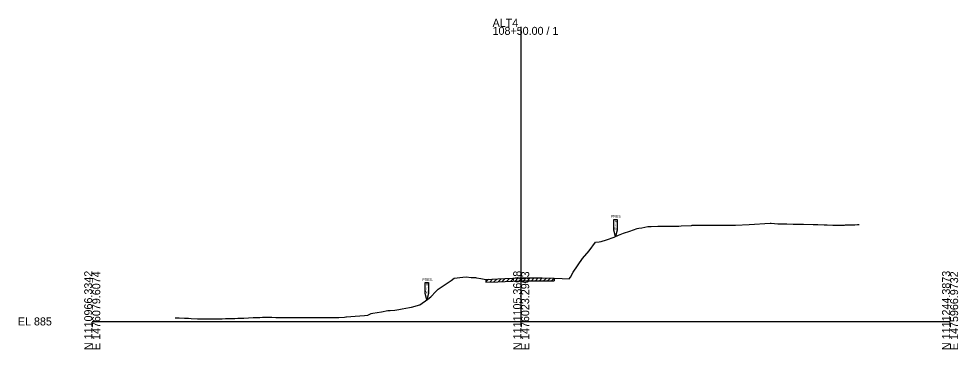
# Model space of a CAD drawing. Extents: x -26 to 1303, y -10 to 19562.
# Drawn here: x 974.3 to 1302.8, y 4990.3 to 5105.7 of the extents above; entities that cross this region are included whole.
import ezdxf

# ---------------------------------------------------------------- set-up
doc = ezdxf.new("R2010")
doc.units = 0
for name, color, linetype in [('RD_GPK_XS_Cell', 7, 'Continuous'), ('RD_XS_ExGround', 7, 'Continuous'), ('RD_XS_ExPaveRet', 7, 'Continuous'), ('RD_XS_ExRW', 7, 'Continuous'), ('RD_XS_TX_Elev_EX', 7, 'Continuous')]:
    doc.layers.add(name, color=color, linetype=linetype)

msp = doc.modelspace()

# ---------------------------------------------------------------- linework, layer by layer
at = {"layer": 'RD_GPK_XS_Cell'}
for p, q in [((1150, 5000), (1150, 5102.87)), ((1000, 5000), (1150, 5000)), ((1150, 5000), (1300, 5000))]:
    msp.add_line(p, q, dxfattribs=at)
at = {"layer": 'RD_XS_ExGround'}
msp.add_lwpolyline([(1028.98, 5001.28), (1029.36, 5001.24), (1030.39, 5001.23), (1032.25, 5001.17), (1033.63, 5001.11), (1034.56, 5001.06), (1036.86, 5000.94), (1040.24, 5000.88), (1042.44, 5000.86), (1043.34, 5000.87), (1045.45, 5000.95), (1046.57, 5000.98), (1048.23, 5001.03), (1049.35, 5001.06), (1049.81, 5001.07), (1050.89, 5001.1), (1053.05, 5001.18), (1056.28, 5001.36), (1058.57, 5001.4), (1059.52, 5001.44), (1061.77, 5001.43), (1062.76, 5001.43), (1064.21, 5001.39), (1065.99, 5001.37), (1067.21, 5001.37), (1069.23, 5001.33), (1072.47, 5001.39), (1074.69, 5001.36), (1075.7, 5001.38), (1078.09, 5001.41), (1078.94, 5001.42), (1080.19, 5001.38), (1081.6, 5001.32), (1082.18, 5001.33), (1083.53, 5001.34), (1085.41, 5001.39), (1086.21, 5001.4), (1088.18, 5001.53), (1088.65, 5001.56), (1088.97, 5001.59), (1091.89, 5001.83), (1095.18, 5002.07), (1096.33, 5002.15), (1097.58, 5002.72), (1098.07, 5002.92), (1101.19, 5003.34), (1103.36, 5003.86), (1104.21, 5003.81), (1105.8, 5003.88), (1107.18, 5004.19), (1108.38, 5004.34), (1111, 5004.87), (1111.63, 5005.01), (1114.52, 5005.79), (1117.3, 5007.74), (1118.46, 5008.58), (1120.14, 5010.42), (1121.02, 5011.3), (1125.53, 5014.29), (1126.62, 5015.05), (1129.55, 5015.4), (1130.73, 5015.55), (1132.5, 5015.39), (1133.97, 5015.3), (1134.33, 5015.24), (1135.94, 5014.94), (1137.66, 5014.69), (1141.8, 5014.82), (1149.6, 5015.19), (1150, 5015.19), (1157.35, 5015.17), (1161.58, 5015.15), (1164.32, 5014.99), (1166.79, 5014.93), (1167.3, 5015.5), (1168.23, 5017.22), (1171.45, 5021.96), (1173.83, 5024.61), (1175.97, 5027.7), (1177.27, 5027.85), (1178.02, 5027.9), (1179.82, 5028.51), (1182.52, 5029.43), (1184.07, 5030.08), (1185.75, 5030.83), (1188.03, 5031.56), (1190.59, 5032.44), (1191.16, 5032.52), (1192.2, 5032.7), (1194.25, 5033.11), (1195.47, 5033.19), (1197.79, 5033.26), (1198.7, 5033.26), (1200.05, 5033.28), (1201.94, 5033.3), (1203.23, 5033.31), (1205.18, 5033.32), (1206, 5033.39), (1209.51, 5033.54), (1209.84, 5033.59), (1210.61, 5033.6), (1211.17, 5033.62), (1213.17, 5033.61), (1219.55, 5033.67), (1220.85, 5033.67), (1224.02, 5033.66), (1224.6, 5033.67), (1224.99, 5033.67), (1229.71, 5033.85), (1237.02, 5034.28), (1237.41, 5034.29), (1239.79, 5034.12), (1240.13, 5034.11), (1240.78, 5034.08), (1242.86, 5034.04), (1245.11, 5034), (1247.69, 5033.93), (1248.71, 5033.91), (1252.07, 5033.86), (1253.73, 5033.9), (1255.98, 5033.76), (1256.96, 5033.69), (1258.98, 5033.56), (1260.2, 5033.57), (1263.07, 5033.67), (1263.44, 5033.69), (1263.97, 5033.68), (1266.67, 5033.75), (1267.57, 5033.84), (1268.25, 5033.85)], dxfattribs=at)
at = {"layer": 'RD_XS_ExPaveRet'}
for p, q in [((1137.66, 5013.83), (1138.55, 5014.72)), ((1137.66, 5014.69), (1137.66, 5013.69)), ((1138.99, 5013.74), (1140.01, 5014.77)), ((1140.45, 5013.78), (1141.47, 5014.81)), ((1141.91, 5013.83), (1142.95, 5014.88)), ((1143.39, 5013.9), (1144.44, 5014.95)), ((1144.88, 5013.97), (1145.92, 5015.02)), ((1146.36, 5014.04), (1147.41, 5015.09)), ((1147.85, 5014.11), (1148.89, 5015.16)), ((1149.33, 5014.18), (1150.34, 5015.19)), ((1150.76, 5014.19), (1151.75, 5015.19)), ((1152.17, 5014.19), (1153.16, 5015.18)), ((1153.58, 5014.19), (1154.57, 5015.18)), ((1154.99, 5014.18), (1155.98, 5015.17)), ((1156.4, 5014.18), (1157.39, 5015.17)), ((1157.81, 5014.17), (1158.8, 5015.16)), ((1159.22, 5014.17), (1160.21, 5015.16)), ((1160.62, 5014.16), (1161.58, 5015.11)), ((1161.58, 5015.15), (1161.58, 5014.15))]:
    msp.add_line(p, q, dxfattribs=at)
msp.add_lwpolyline([(1137.66, 5013.7), (1141.84, 5013.83), (1149.62, 5014.2), (1157.35, 5014.18), (1161.58, 5014.16)], dxfattribs=at)
at = {"layer": 'RD_XS_ExRW'}
for points in [[(1182.45, 5035.65), (1183.55, 5035.65), (1183.55, 5031.82), (1183, 5029.63), (1182.45, 5031.82)], [(1116.45, 5013.55), (1117.55, 5013.55), (1117.55, 5009.72), (1117, 5007.53), (1116.45, 5009.72)]]:
    msp.add_lwpolyline(points, close=True, dxfattribs=at)

# ---------------------------------------------------------------- texts
at = {"layer": 'RD_GPK_XS_Cell'}
for s, p in [('ALT4', (1140, 5102.87)), ('108+50.00 / 1', (1140, 5100.07)), ('EL 885', (974, 4998.6))]:
    msp.add_text(s, height=2.8, dxfattribs=at).set_placement(p)
for s, p in [('N 1110966.3342', (1000, 4990)), ('E 1476079.6074', (1002.8, 4990)), ('N 1111105.3608', (1150, 4990)), ('E 1476023.2903', (1152.8, 4990)), ('N 1111244.3873', (1300, 4990)), ('E 1475966.9732', (1302.8, 4990))]:
    msp.add_text(s, height=2.8, rotation=90, dxfattribs=at).set_placement(p)
at = {"layer": 'RD_XS_ExRW'}
for s, p in [('PRES.', (1181.45, 5036.27)), ('R', (1182.71, 5034.56)), ('/', (1182.83, 5033.24)), ('W', (1182.53, 5031.93)), ('PRES.', (1115.45, 5014.17)), ('W', (1116.53, 5009.83)), ('R', (1116.71, 5012.45)), ('/', (1116.83, 5011.14))]:
    msp.add_text(s, height=0.875, dxfattribs=at).set_placement(p)
at = {"layer": 'RD_XS_TX_Elev_EX'}
msp.add_text('900.19', height=0.5, dxfattribs=at).set_placement((1148.98, 5014.69))

doc.saveas('drawing.dxf')
